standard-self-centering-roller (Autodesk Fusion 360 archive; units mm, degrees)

design "SELF CENTERING ROLLER" references "ROLLER"
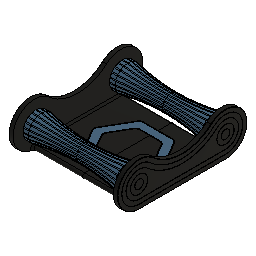
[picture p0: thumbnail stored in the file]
sketch "Sketch1" plane through (0, 0, 0) normal (1, 0, 0) x axis (0, 1, 0)
  line L1 (50, 4) -> (-50, 4)
  line L2 (50, -4) -> (50, 4)
  line L3 (-50, -4) -> (50, -4)
  line L4 (-50, 4) -> (-50, -4)
  line L5 (50, -4) -> (-50, 4)
  line L6 (-50, -4) -> (50, 4)
  line L7 (-78.8675, 0) -> (-64.4338, 25)
  line L8 (-64.4338, -25) -> (-78.8675, 0)
  line L9 (-35.5662, -25) -> (-64.4338, -25)
  line L10 (-21.1325, 0) -> (-35.5662, -25)
  line L11 (-35.5662, 25) -> (-21.1325, 0)
  line L12 (-64.4338, 25) -> (-35.5662, 25)
  line L13 (21.1325, 0) -> (35.5662, 25)
  line L14 (35.5662, -25) -> (21.1325, 0)
  line L15 (64.4338, -25) -> (35.5662, -25)
  line L16 (78.8675, 0) -> (64.4338, -25)
  line L17 (64.4338, 25) -> (78.8675, 0)
  line L18 (35.5662, 25) -> (64.4338, 25)
  line L19 (-35.5662, -25) -> (35.5662, -25)
  line L20 (21.1325, 0) -> (-21.1325, 0)
  line L21 (-61.547, -20) -> (-64.4338, -25)
  line L22 (61.547, -20) -> (-61.547, -20)
  line L23 (64.4338, -25) -> (61.547, -20)
  line L24 (-67.3205, -20) -> (67.3205, -20)
  line L25 (50, 0) -> (-50, 0)
  line L26 (0, -25) -> (0, 0)
  line L27 (0, -25) -> (0, -20)
  line L28 (-50, -20) -> (50, -20)
  line L29 (50, -25) -> (-50, -25)
  line L30 (50, -22.5) -> (50, 0)
  circle C1 centre (-50, 0) radius 4
  circle C2 centre (50, 0) radius 4
  circle C3 centre (50, 0) radius 5
  circle C4 centre (-50, 0) radius 5
  circle C5 centre (-50, 0) radius 25
  circle C6 centre (50, 0) radius 25
  arc A1 centre (-50, -22.5) radius 2.5 clockwise from (-50, -25) to (-50, -20)
  arc A2 centre (50, -22.5) radius 2.5 clockwise from (50, -20) to (50, -25)
  point P6 (0, 0)
  point P1 (0, 0)
  point P7 (-50, 0)
  point P8 (50, 0)
  point P15 (-50, 0)
  point P22 (50, 0)
  point P27 (67.3205, -20)
  point P28 (-67.3205, -20)
  point P29 (-50, 0)
  point P31 (-50, 0)
  point P32 (50, 0)
  point P33 (0, 0)
  point P34 (0, -25)
  point P35 (0, -20)
  point P42 (0, -22.5)
  point P30 (50, 0)
  point P43 (50, 0)
  point P40 (50, -22.5)
  point P44 (50, -22.5)
  point P41 (-50, -22.5)
  point P4 (50, -4)
  point P5 (-50, -4)
  horizontal L1
  perpendicular L1 L2
  parallel L1 L3
  parallel L2 L4
  coincident L5 P6
  coincident L6 P6
  coincident P1 P6
  midpoint L4 P7
  midpoint L2 P8
  tangent L1 C1
  coincident P7 P15
  coincident P8 P22
  horizontal L12
  horizontal L18
  parallel L15 L22
  parallel L17 L23
  parallel L7 L21
  coincident L16 P27
  coincident L8 P28
  parallel L22 L24
  collinear L22 L24
  concentric C1 C5
  tangent L9 C5
  concentric C2 C6
  tangent L15 C6
  coincident P29 P31
  coincident P22 P32
  coincident P6 P33
  midpoint L19 P34
  midpoint L24 P35
  tangent L28 A1
  tangent A1 L29
  parallel L28 L29
  tangent L29 A2
  tangent L28 A2
  midpoint L27 P42
  coincident P30 P43
  coincident P40 P44
  vertical L30
  collinear L22 L28
  collinear L19 L29
  vertical P29 P41
  dimension "d1" diameter C1 = 8 (= "d2")
  dimension "d2" diameter C2 = 8
  dimension "d3" distance P4 P5 = 100
  dimension "d4" distance L9 L12 = 50
  dimension "d5" distance L15 L18 = 50 (= "d4")
  dimension "d6" distance L19 L22 = 5
  dimension "d13" = 1
  dimension "d14" = 1
extrude "Extrude1" new body sketch "MirrorComponent2" profile of L9 L10 L14 L15 L19 L22 L24 C5 C6 L27 L28 A1 L29 A2 against normal blind 58
extrude "Extrude2" add sketch "MirrorComponent2" profile of L1 L2 L3 L4 C1 C2 L9 L10 L14 L15 L19 L20 L21 L22 L23 C3 C4 L24 C5 C6 L25 L27 L28 A1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 along normal blind 5
fillet "Fillet3" radius 50
extrude "Extrude3" add sketch "MirrorComponent2" profile of L2 L4 C1 C2 against normal blind 6
chamfer "Chamfer1" distance 0.6
sketch "Sketch2" plane through (5, 0, 0) normal (1, 0, 0) x axis (0, 1, 0)
  line L1 (63.8564, -25) -> (-63.8564, -25)
  line L2 (78.5788, -0.5) -> (64.7224, -24.5)
  line L3 (64.7224, 24.5) -> (78.5788, 0.5)
  line L4 (36.1436, 25) -> (63.8564, 25)
  line L5 (21.4212, 0.5) -> (35.2776, 24.5)
  line L6 (-20.5551, 0) -> (20.5551, 0)
  line L7 (-35.2776, 24.5) -> (-21.4212, 0.5)
  line L8 (-63.8564, 25) -> (-36.1436, 25)
  line L9 (-78.5788, 0.5) -> (-64.7224, 24.5)
  line L10 (-64.7224, -24.5) -> (-78.5788, -0.5)
  line L11 (-75.8653, 0) -> (-62.9326, 22.4)
  line L12 (-62.9326, -22.4) -> (-75.8653, 0)
  line L13 (-35.5662, -22.4) -> (-62.9326, -22.4)
  line L14 (62.9326, -22.4) -> (-35.5662, -22.4)
  line L15 (75.8653, 0) -> (62.9326, -22.4)
  line L16 (62.9326, 22.4) -> (75.8653, 0)
  line L17 (37.0674, 22.4) -> (62.9326, 22.4)
  line L18 (23.6728, -0.8) -> (37.0674, 22.4)
  line L19 (-20.5551, -2.6) -> (20.5551, -2.6)
  line L20 (-37.0674, 22.4) -> (-23.6728, -0.8)
  line L21 (-62.9326, 22.4) -> (-37.0674, 22.4)
  line L22 (-73.5559, 0) -> (-61.7779, 20.4)
  line L23 (-61.7779, -20.4) -> (-73.5559, 0)
  line L24 (-35.5662, -20.4) -> (-61.7779, -20.4)
  line L25 (61.7779, -20.4) -> (-35.5662, -20.4)
  line L26 (73.5559, 0) -> (61.7779, -20.4)
  line L27 (61.7779, 20.4) -> (73.5559, 0)
  line L28 (38.2221, 20.4) -> (61.7779, 20.4)
  line L29 (25.4049, -1.8) -> (38.2221, 20.4)
  line L30 (-20.5551, -4.6) -> (20.5551, -4.6)
  line L31 (-38.2221, 20.4) -> (-25.4049, -1.8)
  line L32 (-61.7779, 20.4) -> (-38.2221, 20.4)
  line L33 (50, -25) -> (-50, -25)
  arc A1 centre (-63.8564, -24) radius 1 clockwise from (-63.8564, -25) to (-64.7224, -24.5)
  arc A2 centre (63.8564, -24) radius 1 clockwise from (64.7224, -24.5) to (63.8564, -25)
  arc A3 centre (77.7128, 0) radius 1 clockwise from (78.5788, 0.5) to (78.5788, -0.5)
  arc A4 centre (63.8564, 24) radius 1 clockwise from (63.8564, 25) to (64.7224, 24.5)
  arc A5 centre (36.1436, 24) radius 1 clockwise from (35.2776, 24.5) to (36.1436, 25)
  arc A6 centre (20.5551, 1) radius 1 clockwise from (21.4212, 0.5) to (20.5551, 0)
  arc A7 centre (-20.5551, 1) radius 1 clockwise from (-20.5551, 0) to (-21.4212, 0.5)
  arc A8 centre (-36.1436, 24) radius 1 clockwise from (-36.1436, 25) to (-35.2776, 24.5)
  arc A9 centre (-63.8564, 24) radius 1 clockwise from (-64.7224, 24.5) to (-63.8564, 25)
  arc A10 centre (-77.7128, 0) radius 1 clockwise from (-78.5788, -0.5) to (-78.5788, 0.5)
  arc A11 centre (20.5551, 1) radius 3.6 clockwise from (23.6728, -0.8) to (20.5551, -2.6)
  arc A12 centre (-20.5551, 1) radius 3.6 clockwise from (-20.5551, -2.6) to (-23.6728, -0.8)
  arc A13 centre (20.5551, 1) radius 5.6 clockwise from (25.4049, -1.8) to (20.5551, -4.6)
  arc A14 centre (-20.5551, 1) radius 5.6 clockwise from (-20.5551, -4.6) to (-25.4049, -1.8)
  arc A15 centre (50, 0) radius 25 clockwise from (33.3333, 18.6339) to (50, -25)
  arc A16 centre (-50, 0) radius 25 clockwise from (-50, -25) to (-33.3333, 18.6339)
  arc A17 centre (0, 55.9017) radius 50 clockwise from (33.3333, 18.6339) to (-33.3333, 18.6339)
  concentric A6 A11
  concentric A7 A12
  tangent A12 L20
  tangent L18 A11
  tangent A11 L19
  tangent L19 A12
  concentric A6 A13
  concentric A7 A14
  tangent A14 L31
  tangent A13 L30
  tangent L29 A13
  tangent L30 A14
sketch "Sketch3" plane through (0, 0, -20) normal (0, 0, 1) x axis (-1, 0, 0)
  line L1 (58, 50) -> (58, -50)
  line L2 (98.4145, 0) -> (78.2073, -35)
  line L3 (78.2073, 35) -> (98.4145, 0)
  line L4 (37.7927, 35) -> (78.2073, 35)
  line L5 (17.5855, 0) -> (37.7927, 35)
  line L6 (37.7927, -35) -> (17.5855, 0)
  line L7 (78.2073, -35) -> (37.7927, -35)
  line L8 (72.4338, 25) -> (86.8675, 0)
  line L9 (43.5662, 25) -> (72.4338, 25)
  line L10 (29.1325, 0) -> (43.5662, 25)
  line L11 (43.5662, -25) -> (29.1325, 0)
  line L12 (72.4338, -25) -> (43.5662, -25)
  line L13 (86.8675, 0) -> (72.4338, -25)
  line L14 (58, -50) -> (0, -50)
  line L15 (0, 50) -> (58, 50)
  line L16 (0, -50) -> (0, 50)
  point P12 (58, 0)
  midpoint L1 P12
  horizontal L7
  dimension "d23" distance L4 L7 = 70
  dimension "d24" = -10
extrude "Extrude5" cut sketch "Sketch3" profile of L1 L4 L5 L6 L7 L12 L10 L9 L11 against normal blind 2
fillet "Fillet2" radius 5
extrude "Extrude6" add sketch "MirrorComponent2" profile of L1 L3 C1 C2 C3 C4 against normal blind 1.4
chamfer "Chamfer3" distance 1.4
sketch "Sketch4" plane through (5, 0, 0) normal (1, 0, 0) x axis (0, 1, 0)
  line L1 (50, -25) -> (-50, -25)
  line L2 (50, -20) -> (-50, -20)
  line L3 (50, -15) -> (-50, -15)
  arc A1 centre (-50, 0) radius 25 clockwise from (-50, -25) to (-33.3333, 18.6339)
  arc A2 centre (50, 0) radius 25 clockwise from (33.3333, 18.6339) to (50, -25)
  arc A3 centre (0, 55.9017) radius 50 clockwise from (33.3333, 18.6339) to (-33.3333, 18.6339)
  arc A4 centre (50, 0) radius 20 clockwise from (36.6667, 14.9071) to (50, -20)
  arc A5 centre (0, 55.9017) radius 55 clockwise from (36.6667, 14.9071) to (-36.6667, 14.9071)
  arc A6 centre (-50, 0) radius 20 clockwise from (-50, -20) to (-36.6667, 14.9071)
  arc A7 centre (50, 0) radius 15 clockwise from (40, 11.1803) to (50, -15)
  arc A8 centre (0, 55.9017) radius 60 clockwise from (40, 11.1803) to (-40, 11.1803)
  arc A9 centre (-50, 0) radius 15 clockwise from (-50, -15) to (-40, 11.1803)
  circle C1 centre (-50, 0) radius 10
  circle C2 centre (50, 0) radius 10
  circle C3 centre (-50, 0) radius 5
  circle C4 centre (50, 0) radius 5
  concentric A1 C1
  concentric A2 C2
  concentric C1 C3
  concentric C2 C4
  dimension "d64" = 5
  dimension "d67" = -10
  dimension "d69" distance A9 C1 = 5
  dimension "d70" distance A7 C2 = 5
  dimension "d71" distance C2 C4 = 5
  dimension "d72" distance C1 C3 = 5
extrude "Extrude10" cut sketch "Sketch4" profile of L2 A6 A5 A4 L3 A9 A8 A7 C1 C2 C3 C4 against normal blind 0.4
chamfer "Chamfer6" distance 0.4
mirror "Mirror1" mirrorStitchTolerance 0.1
component_insert "Component Insert"
joint "Assemble3" alignAngle 0 alignOffsetX 0 alignOffsetY 0 alignOffsetZ -52
mirror_component "MirrorComponent1"
derived_instance "DerivedInstance1"
derived_instance "DerivedInstance1"
sketch "Sketch1" plane through (0, 0, -22) normal (0, 0, 1) x axis (-1, 0, 0)
  line L1 (75.3205, -35) -> (40.6795, -35)
  line L2 (46.453, -25) -> (69.547, -25)
  line L3 (30.5759, -2.5) -> (42.1229, -22.5)
  line L4 (42.1229, 22.5) -> (30.5759, 2.5)
  line L5 (69.547, 25) -> (46.453, 25)
  line L6 (40.6795, 35) -> (75.3205, 35)
  line L7 (19.0289, 2.5) -> (36.3494, 32.5)
  line L8 (36.3494, -32.5) -> (19.0289, -2.5)
  line L9 (96.9711, -2.5) -> (79.6506, -32.5)
  line L10 (79.6506, 32.5) -> (96.9711, 2.5)
  line L11 (85.4241, 2.5) -> (73.8771, 22.5)
  line L12 (73.8771, -22.5) -> (85.4241, -2.5)
  line L13 (40.6795, 35) -> (75.3205, 35)
  line L14 (19.0289, 2.5) -> (36.3494, 32.5)
  line L15 (36.3494, -32.5) -> (19.0289, -2.5)
  line L16 (75.3205, -35) -> (40.6795, -35)
  line L17 (96.9711, -2.5) -> (79.6506, -32.5)
  line L18 (79.6506, 32.5) -> (96.9711, 2.5)
  line L19 (69.547, 25) -> (46.453, 25)
  line L20 (85.4241, 2.5) -> (73.8771, 22.5)
  line L21 (73.8771, -22.5) -> (85.4241, -2.5)
  line L22 (46.453, -25) -> (69.547, -25)
  line L23 (30.5759, -2.5) -> (42.1229, -22.5)
  line L24 (42.1229, 22.5) -> (30.5759, 2.5)
  line L25 (19.2021, 2.4) -> (36.5226, 32.4)
  line L26 (36.5226, -32.4) -> (19.2021, -2.4)
  line L27 (75.3205, -34.8) -> (40.6795, -34.8)
  line L28 (96.7979, -2.4) -> (79.4774, -32.4)
  line L29 (79.4774, 32.4) -> (96.7979, 2.4)
  line L30 (40.6795, 34.8) -> (75.3205, 34.8)
  line L31 (69.547, 25.2) -> (46.453, 25.2)
  line L32 (41.9497, 22.6) -> (30.4027, 2.6)
  line L33 (30.4027, -2.6) -> (41.9497, -22.6)
  line L34 (46.453, -25.2) -> (69.547, -25.2)
  line L35 (74.0503, -22.6) -> (85.5973, -2.6)
  line L36 (85.5973, 2.6) -> (74.0503, 22.6)
  line L37 (92.641, 0) -> (75.3205, -30)
  line L38 (75.3205, 30) -> (92.641, 0)
  line L39 (40.6795, 30) -> (75.3205, 30)
  line L40 (23.359, 0) -> (40.6795, 30)
  line L41 (40.6795, -30) -> (23.359, 0)
  line L42 (75.3205, -30) -> (40.6795, -30)
  arc A1 centre (40.6795, -30) radius 5 clockwise from (40.6795, -35) to (36.3494, -32.5)
  arc A2 centre (46.453, -20) radius 5 clockwise from (46.453, -25) to (42.1229, -22.5)
  arc A3 centre (34.906, 0) radius 5 clockwise from (30.5759, -2.5) to (30.5759, 2.5)
  arc A4 centre (46.453, 20) radius 5 clockwise from (42.1229, 22.5) to (46.453, 25)
  arc A5 centre (40.6795, 30) radius 5 clockwise from (36.3494, 32.5) to (40.6795, 35)
  arc A6 centre (23.359, 0) radius 5 clockwise from (19.0289, -2.5) to (19.0289, 2.5)
  arc A7 centre (75.3205, -30) radius 5 clockwise from (79.6506, -32.5) to (75.3205, -35)
  arc A8 centre (92.641, 0) radius 5 clockwise from (96.9711, 2.5) to (96.9711, -2.5)
  arc A9 centre (75.3205, 30) radius 5 clockwise from (75.3205, 35) to (79.6506, 32.5)
  arc A10 centre (69.547, 20) radius 5 clockwise from (69.547, 25) to (73.8771, 22.5)
  arc A11 centre (81.094, 0) radius 5 clockwise from (85.4241, 2.5) to (85.4241, -2.5)
  arc A12 centre (69.547, -20) radius 5 clockwise from (73.8771, -22.5) to (69.547, -25)
  arc A13 centre (40.6795, 30) radius 5 clockwise from (36.3494, 32.5) to (40.6795, 35)
  arc A14 centre (23.359, 0) radius 5 clockwise from (19.0289, -2.5) to (19.0289, 2.5)
  arc A15 centre (40.6795, -30) radius 5 clockwise from (40.6795, -35) to (36.3494, -32.5)
  arc A16 centre (75.3205, -30) radius 5 clockwise from (79.6506, -32.5) to (75.3205, -35)
  arc A17 centre (92.641, 0) radius 5 clockwise from (96.9711, 2.5) to (96.9711, -2.5)
  arc A18 centre (75.3205, 30) radius 5 clockwise from (75.3205, 35) to (79.6506, 32.5)
  arc A19 centre (69.547, 20) radius 5 clockwise from (69.547, 25) to (73.8771, 22.5)
  arc A20 centre (81.094, 0) radius 5 clockwise from (85.4241, 2.5) to (85.4241, -2.5)
  arc A21 centre (69.547, -20) radius 5 clockwise from (73.8771, -22.5) to (69.547, -25)
  arc A22 centre (46.453, -20) radius 5 clockwise from (46.453, -25) to (42.1229, -22.5)
  arc A23 centre (34.906, 0) radius 5 clockwise from (30.5759, -2.5) to (30.5759, 2.5)
  arc A24 centre (46.453, 20) radius 5 clockwise from (42.1229, 22.5) to (46.453, 25)
  arc A25 centre (23.359, 0) radius 4.8 clockwise from (19.2021, -2.4) to (19.2021, 2.4)
  arc A26 centre (40.6795, -30) radius 4.8 clockwise from (40.6795, -34.8) to (36.5226, -32.4)
  arc A27 centre (75.3205, -30) radius 4.8 clockwise from (79.4774, -32.4) to (75.3205, -34.8)
  arc A28 centre (92.641, 0) radius 4.8 clockwise from (96.7979, 2.4) to (96.7979, -2.4)
  arc A29 centre (75.3205, 30) radius 4.8 clockwise from (75.3205, 34.8) to (79.4774, 32.4)
  arc A30 centre (40.6795, 30) radius 4.8 clockwise from (36.5226, 32.4) to (40.6795, 34.8)
  arc A31 centre (69.547, 20) radius 5.2 clockwise from (69.547, 25.2) to (74.0503, 22.6)
  arc A32 centre (46.453, 20) radius 5.2 clockwise from (41.9497, 22.6) to (46.453, 25.2)
  arc A33 centre (34.906, 0) radius 5.2 clockwise from (30.4027, -2.6) to (30.4027, 2.6)
  arc A34 centre (46.453, -20) radius 5.2 clockwise from (46.453, -25.2) to (41.9497, -22.6)
  arc A35 centre (69.547, -20) radius 5.2 clockwise from (74.0503, -22.6) to (69.547, -25.2)
  arc A36 centre (81.094, 0) radius 5.2 clockwise from (85.5973, 2.6) to (85.5973, -2.6)
  circle C1 centre (32.0192, -15) radius 2.5
  circle C2 centre (32.0192, 15) radius 2.5
  circle C3 centre (83.9808, -15) radius 2.5
  circle C4 centre (83.9808, 15) radius 2.5
  circle C5 centre (32.0192, -15) radius 2.3
  circle C6 centre (32.0192, 15) radius 2.3
  circle C7 centre (83.9808, 15) radius 2.3
  circle C8 centre (83.9808, -15) radius 2.3
  point P116 (32.0192, -15)
  point P117 (32.0192, 15)
  point P118 (83.9808, -15)
  point P119 (83.9808, 15)
  midpoint L41 P116
  midpoint L40 P117
  coincident L37 P118
  midpoint L38 P119
  midpoint L37 P118
  concentric C1 C5
  concentric C2 C6
  concentric C4 C7
  concentric C3 C8
  dimension "d37" = -0.2
  dimension "d38" = -0.2
  dimension "d53" = -5
  dimension "d54" diameter C1 = 5
  dimension "d55" diameter C3 = 5 (= "d54")
  dimension "d56" diameter C2 = 5 (= "d54")
  dimension "d57" diameter C4 = 5 (= "d54")
  dimension "d90" diameter C5 = 4.6
  dimension "d91" diameter C8 = 4.6 (= "d90")
  dimension "d92" diameter C6 = 4.6 (= "d90")
  dimension "d93" diameter C7 = 4.6 (= "d90")
extrude "Extrude7" new body sketch "Sketch1" profile of A30 L27 A28 L28 A27 L25 A26 L30 L29 L26 A29 A25 A36 L32 A35 L35 A34 L33 L36 A33 A32 L31 L34 A31 along normal blind 2
work_plane "WorkPlane1"
split "Split1" bodies "SIDE B"
chamfer "Chamfer4" distance 0.6
extrude "Extrude8" cut sketch "Sketch1" profile of L38 L41 L40 L37 C1 C2 C3 C4 no distance stored
extrude "Extrude9" add sketch "Sketch1" profile of L38 L41 L40 L37 C1 C2 C3 C4 against normal blind 3
extrude "Extrude14" sketch "Sketch1" profile of L38 L41 L40 L37 C1 C2 C3 C4 C5 C6 C7 C8 blind -1 from offset -1
extrude "Extrude16" cut of existing geometry blind -0.1
chamfer "Chamfer7" distance 0.2
chamfer "Chamfer5" distance 0.4
sketch "Sketch5" plane through (0, 0, -22) normal (0, 0, 1) x axis (-1, 0, 0)
  line L1 (58, -25) -> (58, -35)
  line L2 (46.453, -25) -> (58, -25)
  line L3 (30.5759, -2.5) -> (42.1229, -22.5)
  line L4 (42.1229, 22.5) -> (30.5759, 2.5)
  line L5 (58, 25) -> (46.453, 25)
  line L6 (58, 35) -> (58, 25)
  line L7 (40.6795, 35) -> (58, 35)
  line L8 (19.0289, 2.5) -> (36.3494, 32.5)
  line L9 (36.3494, -32.5) -> (19.0289, -2.5)
  line L10 (58, -35) -> (40.6795, -35)
  line L11 (54, -30) -> (58, -30)
  line L12 (54, 30) -> (58, 30)
  line L13 (50, 29) -> (58, 29)
  line L14 (50, 31) -> (50, 29)
  line L15 (58, 31) -> (50, 31)
  line L16 (58, 29) -> (58, 31)
  line L17 (50, 31) -> (58, 29)
  line L18 (58, 31) -> (50, 29)
  line L19 (50, -31) -> (58, -31)
  line L20 (50, -29) -> (50, -31)
  line L21 (58, -29) -> (50, -29)
  line L22 (58, -31) -> (58, -29)
  line L23 (50, -29) -> (58, -31)
  line L24 (58, -29) -> (50, -31)
  circle C1 centre (32.0192, -15) radius 2.5
  circle C2 centre (32.0192, 15) radius 2.5
  arc A1 centre (46.453, -20) radius 5 clockwise from (46.453, -25) to (42.1229, -22.5)
  arc A2 centre (34.906, 0) radius 5 clockwise from (30.5759, -2.5) to (30.5759, 2.5)
  arc A3 centre (46.453, 20) radius 5 clockwise from (42.1229, 22.5) to (46.453, 25)
  arc A4 centre (40.6795, 30) radius 5 clockwise from (36.3494, 32.5) to (40.6795, 35)
  arc A5 centre (23.359, 0) radius 5 clockwise from (19.0289, -2.5) to (19.0289, 2.5)
  arc A6 centre (40.6795, -30) radius 5 clockwise from (40.6795, -35) to (36.3494, -32.5)
  circle C3 centre (54, 30) radius 2
  circle C4 centre (54, -30) radius 2
  point P26 (58, -30)
  point P28 (58, 30)
  point P29 (54, 30)
  point P30 (54, 30)
  point P35 (54, 30)
  point P31 (58, 29)
  point P27 (54, -30)
  point P36 (54, -30)
  point P41 (54, -30)
  point P37 (58, -31)
  point P38 (50, -31)
  point P39 (50, -29)
  midpoint L1 P26
  perpendicular L1 L11
  midpoint L6 P28
  perpendicular L6 L12
  coincident P29 P30
  horizontal L13
  perpendicular L13 L14
  parallel L13 L15
  parallel L14 L16
  coincident L17 P35
  coincident L18 P35
  coincident L6 P31
  coincident P30 P35
  coincident P27 P36
  horizontal L19
  perpendicular L19 L20
  parallel L19 L21
  parallel L20 L22
  coincident L23 P41
  coincident L24 P41
  coincident L1 P37
  coincident P36 P41
  dimension "d73" diameter C3 = 4
  dimension "d74" distance L13 L15 = 2
  dimension "d75" distance P28 P29 = 4
  dimension "d76" diameter C4 = 4 (= "d73")
  dimension "d77" distance P37 P38 = 8
  dimension "d78" distance P38 P39 = 2
offset_faces "OffsetFaces2" distance -0.1
combine "Combine1"
offset_faces "OffsetFaces3" distance -0.05
sketch "Sketch8" plane through (0, 0, -24.9) normal (0, 0, -1) x axis (1, 0, 0)
  circle C1 centre (-83.9808, -15) radius 1.8
  circle C2 centre (-32.0192, -15) radius 1.5
  circle C3 centre (-32.0192, 15) radius 1.5
  circle C4 centre (-83.9808, 15) radius 1.5
  circle C5 centre (-83.9808, -15) radius 1.5
  circle C6 centre (-32.0192, -15) radius 2
  point P5 (-83.9808, 15)
  point P7 (-83.9808, 15)
  point P4 (-32.0192, 15)
  point P8 (-32.0192, 15)
  point P3 (-32.0192, -15)
  point P9 (-32.0192, -15)
  concentric C1 C5
  coincident P5 P7
  coincident P4 P8
  coincident P3 P9
  dimension "d100" diameter C5 = 3
  dimension "d101" diameter C4 = 3 (= "d100")
  dimension "d102" diameter C3 = 3 (= "d101")
  dimension "d103" diameter C2 = 3 (= "d101")
sketch "Sketch9" plane through (-58, 0, 0) normal (1, 0, 0) x axis (0, 1, 0)
  line L1 (25, -22) -> (35, -22)
  line L2 (-35, -20) -> (-35, -22)
  line L3 (-50, -20) -> (-35, -20)
  line L4 (50, -25) -> (-50, -25)
  line L5 (35, -20) -> (50, -20)
  line L6 (35, -22) -> (35, -20)
  line L7 (25, -20) -> (25, -22)
  line L8 (-25, -20) -> (25, -20)
  line L9 (-25, -22) -> (-25, -20)
  line L10 (52.5, -22.5) -> (-52.5, -22.5)
  line L11 (-40, -23.5) -> (-45, -23.5)
  line L12 (-45, -21.5) -> (-40, -21.5)
  line L13 (-40, -22.5) -> (-45, -22.5)
  line L14 (2.5, -23.5) -> (-2.5, -23.5)
  line L15 (-2.5, -21.5) -> (2.5, -21.5)
  line L16 (2.5, -22.5) -> (-2.5, -22.5)
  line L17 (45, -23.5) -> (40, -23.5)
  line L18 (40, -21.5) -> (45, -21.5)
  line L19 (45, -22.5) -> (40, -22.5)
  line L20 (-35, -22) -> (-25, -22)
  arc A1 centre (-50, -22.5) radius 2.5 clockwise from (-50, -25) to (-50, -20)
  arc A2 centre (50, -22.5) radius 2.5 clockwise from (50, -20) to (50, -25)
  circle C1 centre (-42.5, -22.5) radius 0.9
  circle C2 centre (0, -22.5) radius 0.9
  circle C3 centre (42.5, -22.5) radius 0.9
  arc A3 centre (-40, -22.5) radius 1 clockwise from (-40, -21.5) to (-40, -23.5)
  arc A4 centre (-45, -22.5) radius 1 clockwise from (-45, -23.5) to (-45, -21.5)
  arc A5 centre (2.5, -22.5) radius 1 clockwise from (2.5, -21.5) to (2.5, -23.5)
  arc A6 centre (-2.5, -22.5) radius 1 clockwise from (-2.5, -23.5) to (-2.5, -21.5)
  arc A7 centre (45, -22.5) radius 1 clockwise from (45, -21.5) to (45, -23.5)
  arc A8 centre (40, -22.5) radius 1 clockwise from (40, -23.5) to (40, -21.5)
  point P20 (-52.5, -22.5)
  point P21 (52.5, -22.5)
  point P19 (42.5, -22.5)
  point P18 (0, -22.5)
  point P17 (-42.5, -22.5)
  point P27 (-40, -22.5)
  point P28 (-42.5, -22.5)
  point P34 (2.5, -22.5)
  point P35 (0, -22.5)
  point P41 (45, -22.5)
  point P42 (42.5, -22.5)
  point P26 (-45, -22.5)
  point P40 (40, -22.5)
  point P33 (-2.5, -22.5)
  midpoint A1 P20
  midpoint A2 P21
  coincident P19 L10
  coincident P18 L10
  coincident P17 L10
  midpoint P18 L10
  tangent L11 A3
  tangent A3 L12
  parallel L11 L12
  tangent L12 A4
  tangent L11 A4
  coincident L10 P27
  parallel L10 L13
  coincident P17 P28
  midpoint L13 P28
  tangent L14 A5
  tangent A5 L15
  parallel L14 L15
  tangent L15 A6
  tangent L14 A6
  coincident L10 P34
  parallel L10 L16
  coincident P18 P35
  midpoint L16 P35
  tangent L17 A7
  tangent A7 L18
  parallel L17 L18
  tangent L18 A8
  tangent L17 A8
  coincident L10 P41
  parallel L10 L19
  coincident P19 P42
  midpoint L19 P42
  dimension "d108" diameter C1 = 1.8
  dimension "d109" diameter C2 = 1.8
  dimension "d110" diameter C3 = 1.8
  dimension "d111" distance P17 P20 = 10
  dimension "d112" distance P19 P21 = 10
  dimension "d115" distance L11 L12 = 2
  dimension "d116" distance P26 P27 = 5
  dimension "d117" distance P40 P41 = 5
  dimension "d118" distance L17 L18 = 2
  dimension "d119" distance L14 L15 = 2
  dimension "d120" distance P33 P34 = 5
extrude "Extrude17" cut sketch "Sketch9" profile of C1 C2 C3 L10 L11 A3 L12 A4 L14 A5 L15 A6 L17 A7 L18 A8 distance -20
sketch "Sketch10" plane through (-58, 0, 0) normal (1, 0, 0) x axis (0, 1, 0)
  line L1 (-2.5, -23.5) -> (2.5, -23.5)
  line L2 (2.5, -21.5) -> (-2.5, -21.5)
  line L3 (40, -23.5) -> (45, -23.5)
  line L4 (45, -21.5) -> (40, -21.5)
  line L5 (-45, -23.5) -> (-40, -23.5)
  line L6 (-40, -21.5) -> (-45, -21.5)
  line L7 (-32.8238, -22) -> (-32.8238, -25)
  line L8 (-35, -22) -> (-32.8238, -22)
  line L9 (-35, -20) -> (-35, -22)
  line L10 (-50, -20) -> (-35, -20)
  line L11 (50, -25) -> (-50, -25)
  line L12 (35, -20) -> (50, -20)
  line L13 (35, -22) -> (35, -20)
  line L14 (32.8238, -22) -> (35, -22)
  line L15 (32.8238, -25) -> (32.8238, -22)
  line L16 (27.1762, -25) -> (32.8238, -25)
  line L17 (27.1762, -22) -> (27.1762, -25)
  line L18 (25, -22) -> (27.1762, -22)
  line L19 (25, -20) -> (25, -22)
  line L20 (-25, -20) -> (25, -20)
  line L21 (-25, -22) -> (-25, -20)
  line L22 (-27.1762, -22) -> (-25, -22)
  line L23 (-27.1762, -25) -> (-27.1762, -22)
  line L24 (-32.8238, -25) -> (-27.1762, -25)
  line L25 (-45, -23.3) -> (-40, -23.3)
  line L26 (-40, -21.7) -> (-45, -21.7)
  arc A1 centre (-2.5, -22.5) radius 1 clockwise from (-2.5, -23.5) to (-2.5, -21.5)
  arc A2 centre (2.5, -22.5) radius 1 clockwise from (2.5, -21.5) to (2.5, -23.5)
  arc A3 centre (40, -22.5) radius 1 clockwise from (40, -23.5) to (40, -21.5)
  arc A4 centre (45, -22.5) radius 1 clockwise from (45, -21.5) to (45, -23.5)
  arc A5 centre (-45, -22.5) radius 1 clockwise from (-45, -23.5) to (-45, -21.5)
  arc A6 centre (-40, -22.5) radius 1 clockwise from (-40, -21.5) to (-40, -23.5)
  arc A7 centre (-50, -22.5) radius 2.5 clockwise from (-50, -25) to (-50, -20)
  arc A8 centre (50, -22.5) radius 2.5 clockwise from (50, -20) to (50, -25)
  arc A9 centre (-45, -22.5) radius 0.8 clockwise from (-45, -23.3) to (-45, -21.7)
  arc A10 centre (-40, -22.5) radius 0.8 clockwise from (-40, -21.7) to (-40, -23.3)
  dimension "d121" = 0.2
extrude "Extrude18" new body sketch "Sketch10" profile of L26 A10 A9 L25 distance -19 bodies "standard_internal_support (x3)"
chamfer "Chamfer8" distance 0.5
chamfer "Chamfer9" distance 0.6
rectangular_pattern "R-Pattern1" uSpaceDistance -85 vSpaceDistance 0 bodies "INTERNAL SUPPORT (1)", "INTERNAL SUPPORT (2)"
remove_instance "RemoveInstance1"
mirror_component "MirrorComponent2"
derived_instance "DerivedInstance2"
derived_instance "DerivedInstance1"
derived_instance "DerivedInstance2"
derived_instance "DerivedInstance1"
chamfer "Chamfer10" distance 2
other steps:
derived_base_feature "Derived Base Feature1"
derived_base_feature "Derived Base Feature1"
derived_base_feature "Derived Base Feature1"
derived_base_feature "Derived Base Feature1"
derived_base_feature "Derived Base Feature1"
derived_base_feature "Derived Base Feature1"
create_component "CreateComponent1"
create_component "CreateComponent2"
create_component "CreateComponent3"
joint_origin "JointOrigin4"
create_component "CreateComponent4"
create_component "CreateComponent5"
create_component "CreateComponent6"
create_component "CreateComponent7"
named bodies: "standard_roller_body (x2)", "standard_hex_insert (x1)", "SIDE B", "standard_internal_support (x3)", "INTERNAL SUPPORT (1)", "INTERNAL SUPPORT (2)"

design "Bearing"
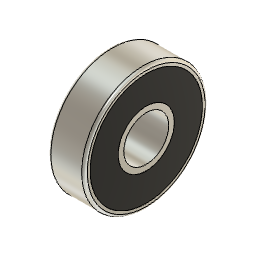
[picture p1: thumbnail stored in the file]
base_feature "Base Feature"
sketch "Sketch1" plane through (11, 0, 0) normal (1, 0, 0) x axis (0, 0, -1)
  circle C1 centre (0, 111) radius 4
  circle C2 centre (0, 111) radius 5
  circle C3 centre (0, 111) radius 4
  circle C4 centre (0, 111) radius 11
  concentric C1 C3
  concentric C3 C4
  dimension "d121" diameter C4 = 22
  dimension "d122" diameter C3 = 8
extrude "Extrude1" new body sketch "Sketch1" along normal blind 6.5
fillet "Fillet1" radius 0.5
sketch "Sketch2" plane through (17.5, 0, 0) normal (1, 0, 0) x axis (0, 1, 0)
  circle C1 centre (111, 0) radius 4
  circle C2 centre (111, 0) radius 10.5
  circle C3 centre (111, 0) radius 10
  circle C4 centre (111, 0) radius 5
  concentric C1 C3
  concentric C3 C4
  dimension "d3" distance C1 C4 = 1
  dimension "d4" distance C2 C3 = 0.5
extrude "Extrude2" cut sketch "Sketch2" profile of C3 C4 against normal blind 6.5
extrude "Extrude3" new body sketch "Sketch2" profile of C3 C4 against normal blind 6.5

design "ROLLER" references "Bearing"
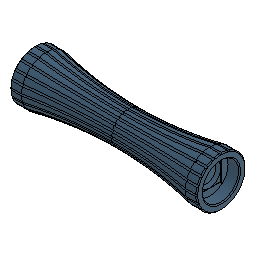
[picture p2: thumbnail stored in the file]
sketch "Sketch2" plane through (0, 0, 0) normal (0, 0, 1) x axis (1, 0, 0)
  line L1 (50, 15) -> (-50, 15)
  line L2 (50, -15) -> (50, 15)
  line L3 (-50, -15) -> (50, -15)
  line L4 (-50, 15) -> (-50, -15)
  line L5 (50, -15) -> (-50, 15)
  line L6 (-50, -15) -> (50, 15)
  line L7 (-57, 15) -> (-50, 15)
  line L8 (-57, 11.05) -> (-57, 15)
  line L9 (-50, 11.05) -> (-57, 11.05)
  line L10 (-50, 15) -> (-50, 11.05)
  line L11 (-50, 0) -> (0, 0)
  line L12 (50, 0) -> (-50, 0)
  line L13 (0, 15) -> (0, 0)
  line L14 (-48, 0) -> (-50, 0)
  line L15 (-48, 7) -> (-48, 0)
  line L16 (-50, 7) -> (-48, 7)
  line L17 (-50, 0) -> (-50, 7)
  arc A1 centre (0, 259.949) radius 250 clockwise from (50, 15) to (-50, 15)
  point P6 (0, 0)
  point P1 (0, 0)
  point P10 (0, 0)
  point P11 (-50, 0)
  point P13 (50, 0)
  point P14 (0, 0)
  point P15 (0, 15)
  point P2 (-50, 15)
  point P7 (-57, 15)
  point P16 (-48, 0)
  point P17 (-48, 7)
  point P18 (-50, 7)
  horizontal L1
  perpendicular L1 L2
  parallel L1 L3
  parallel L2 L4
  coincident L5 P6
  coincident L6 P6
  coincident P1 P6
  horizontal L7
  vertical L8
  horizontal L9
  vertical L10
  coincident P6 P10
  midpoint L4 P11
  midpoint L2 P13
  coincident P1 P14
  midpoint L1 P15
  horizontal L14
  vertical L15
  horizontal L16
  vertical L17
  dimension "d2" distance P10 P11 = 50
  dimension "d3" distance L9 P11 = 11.05
  dimension "d4" distance L1 L3 = 30
  dimension "d5" radius A1 = 250
  dimension "d6" distance P2 P7 = 7
  dimension "d26" distance P16 P17 = 7
  dimension "d27" distance P17 P18 = 2
revolve "Revolve1" sketch "Sketch2" AlongAngle 360
mirror "Mirror1" mirrorStitchTolerance 0.1
component_insert "Component Insert1"
joint "Assemble1" alignAngle 0 alignOffsetX 0 alignOffsetY 0 alignOffsetZ 0
component_insert "Component Insert2"
joint "Assemble2" alignAngle 0 alignOffsetX 0 alignOffsetY 0 alignOffsetZ 0
chamfer "Chamfer1" distance 0.6
sketch "Sketch3" plane through (50, 0, 0) normal (1, 0, 0) x axis (0, 1, 0)
  line L1 (7, -8.55) -> (-7, -8.55)
  line L2 (7, 8.55) -> (7, -8.55)
  line L3 (-7, 8.55) -> (7, 8.55)
  line L4 (-7, -8.55) -> (-7, 8.55)
  line L5 (7, 8.55) -> (-7, -8.55)
  line L6 (-7, 8.55) -> (7, -8.55)
  line L7 (8.55, -7) -> (-8.55, -7)
  line L8 (8.55, 7) -> (8.55, -7)
  line L9 (-8.55, 7) -> (8.55, 7)
  line L10 (-8.55, -7) -> (-8.55, 7)
  line L11 (8.55, 7) -> (-8.55, -7)
  line L12 (-8.55, 7) -> (8.55, -7)
  circle C1 centre (0, 0) radius 7
  circle C2 centre (0, 0) radius 11.05
  circle C3 centre (0, 0) radius 7
  point P7 (0, 0)
  point P3 (-7, -8.55)
  point P2 (0, 0)
  point P12 (0, 0)
  point P8 (-8.55, -7)
  horizontal L1
  perpendicular L1 L2
  parallel L1 L3
  parallel L2 L4
  coincident L5 P7
  coincident L6 P7
  coincident C2 P3
  coincident P2 P7
  horizontal L7
  perpendicular L7 L8
  parallel L7 L9
  parallel L8 L10
  coincident L11 P12
  coincident L12 P12
  coincident C2 P8
  coincident P7 P12
  tangent C1 L2
  tangent L7 C3
extrude "Extrude2" cut sketch "Sketch3" profile of C1 C2 L1 L2 L3 L4 L7 L9 C3 against normal blind 0.2
extrude "Extrude3" cut sketch "Sketch3" profile of C1 L2 L4 L7 L9 C3 against normal blind 0.4
chamfer "Chamfer2" distance 1.6
split "Split1"
sketch "Sketch1" plane through (0, 0, 0) normal (1, 0, 0) x axis (0, 1, 0)
  line L1 (5.7735, 0) -> (2.8868, -5)
  line L2 (2.8868, 5) -> (5.7735, 0)
  line L3 (-2.8868, 5) -> (2.8868, 5)
  line L4 (-5.7735, 0) -> (-2.8868, 5)
  line L5 (-2.8868, -5) -> (-5.7735, 0)
  line L6 (2.8868, -5) -> (-2.8868, -5)
  line L7 (2.829, 4.9) -> (5.658, 0)
  line L8 (-2.829, 4.9) -> (2.829, 4.9)
  line L9 (-5.658, 0) -> (-2.829, 4.9)
  line L10 (-2.829, -4.9) -> (-5.658, 0)
  line L11 (2.829, -4.9) -> (-2.829, -4.9)
  line L12 (5.658, 0) -> (2.829, -4.9)
  point P1 (0, 0)
  point P8 (0, 0)
  coincident P1 P8
  horizontal L6
  dimension "d19" distance L1 L4 = 10
  dimension "d20" = -0.1
extrude "Extrude1" cut sketch "Sketch1" distance -30
extrude "Extrude1" new body sketch "Sketch1" profile of L12 L11 L10 L9 L8 L7 distance 29
chamfer "Chamfer1" distance 0.6
ground "Ground1"
component_from_bodies "Body->Comp"
as_built_joint "As-built1"
sketch "Sketch2" plane through (0, 0, 0) normal (0, 1, 0) x axis (1, 0, 0)
  line L1 (50, 15) -> (50, -15)
  line L2 (0, 9.949) -> (0, -9.949)
  line L3 (50, 15) -> (50, -15)
  line L4 (56.4, 15) -> (56.4, -15)
  line L5 (56.4, 15) -> (56.4, -15)
  line L6 (57, -14.4) -> (57, 14.4)
  line L7 (-50, -15) -> (-56.4, -15)
  line L8 (-56.4, 15) -> (-50, 15)
  line L9 (-57, 14.4) -> (-56.4, 15)
  line L10 (-56.4, -15) -> (-57, -14.4)
  line L11 (56.4, 15) -> (57, 14.4)
  line L12 (57, -14.4) -> (56.4, -15)
  line L13 (56.4, -15) -> (50, -15)
  line L14 (50, 15) -> (56.4, 15)
  line L15 (61.4, -15) -> (56.4, -15)
  line L16 (-61, -15) -> (-56.4, -15)
  arc A1 centre (0, -259.949) radius 250 between (50, -15) and (0, -9.949)
  arc A2 centre (0, 259.949) radius 250 between (0, 9.949) and (50, 15)
  arc A3 centre (0, -259.949) radius 250 between (0, -9.949) and (-50, -15)
  arc A4 centre (0, 259.949) radius 250 between (-50, 15) and (0, 9.949)
  point P8 (56.4, -15)
  point P42 (56.4, -15)
  point P33 (-56.4, -15)
  point P44 (-56.4, -15)
  point P43 (61.4, -15)
  coincident P8 P42
  perpendicular L4 L15
  coincident P33 P44
  parallel L7 L16
  dimension "d29" distance P42 P43 = 5
pipe "Pipe1" SectionSize 1.2 SectionThickness 0.3
circular_pattern "C-Pattern1" countU 20 TotalAngle 360
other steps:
base_feature "Base Feature"
create_component "CreateComponent1"
joint_origin "JointOrigin1"
joint_origin "JointOrigin2"
create_component "CreateComponent3"
remove_body "RemoveBody1"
